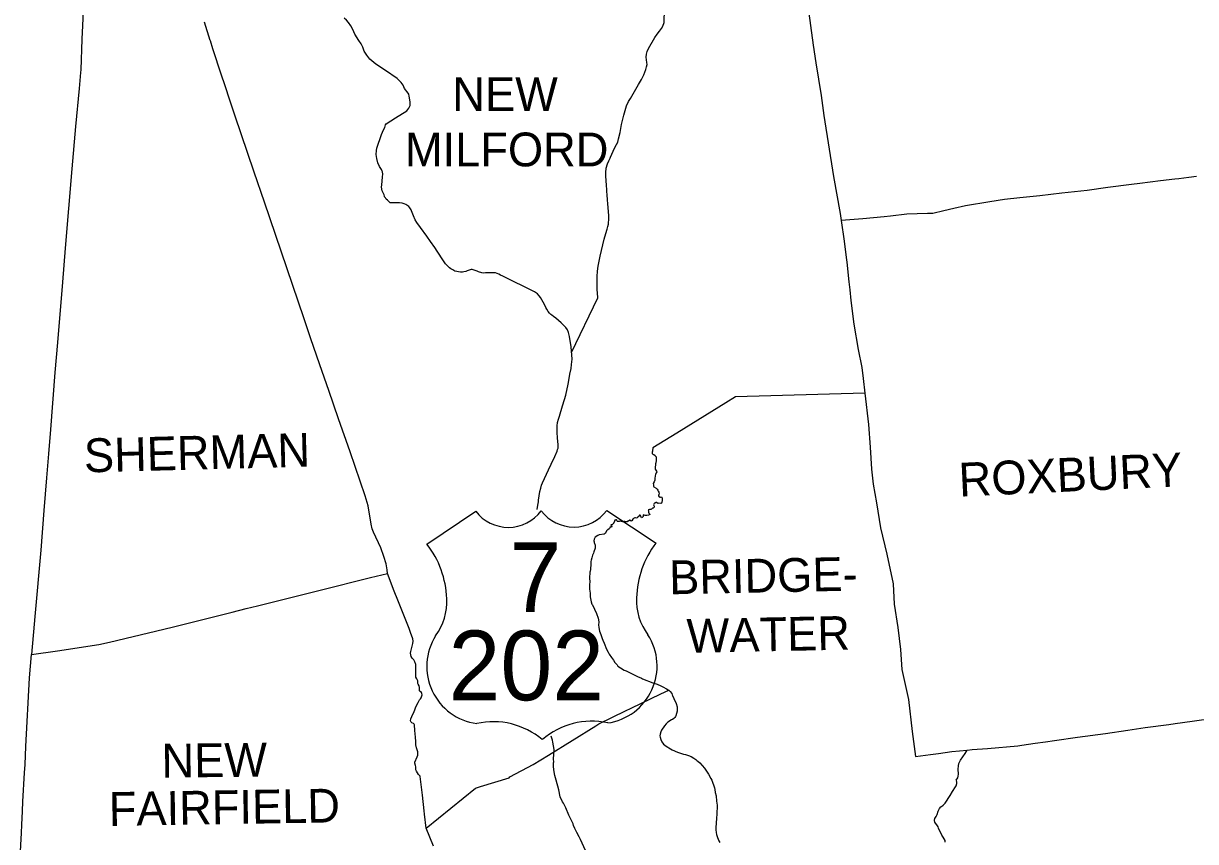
# Model space of a CAD drawing. Extents: x 0 to 2603, y -226 to 830.
# Drawn here: x 53.86 to 100.65, y 575 to 607.68 of the extents above; entities that cross this region are included whole.
import ezdxf

# ---------------------------------------------------------------- set-up
doc = ezdxf.new("R2010")
doc.units = 0
for name, color, linetype in [('CT_TSH_Map_Town_Limits', 7, 'Continuous'), ('CT_TSH_Map_Town_Text', 7, 'Continuous'), ('CT_TSH_Map_US_and_State_Routes', 7, 'Continuous')]:
    doc.layers.add(name, color=color, linetype=linetype)

msp = doc.modelspace()

# ---------------------------------------------------------------- linework, layer by layer
at = {"layer": 'CT_TSH_Map_Town_Limits'}
for points in [[(80.796, 620.456), (80.848, 619.874), (80.911, 619.122), (80.967, 618.543), (81.013, 617.971), (81.031, 617.779), (81.465, 614.798), (81.68, 614.608), (82.055, 614.284), (82.614, 613.822), (84.555, 612.035), (84.765, 611.835), (85.042, 609.477), (85.111, 608.892), (85.384, 606.809), (85.491, 606.099), (85.7, 604.798), (85.811, 603.998), (86.203, 601.565), (86.464, 600.083), (86.508, 599.804)], [(56.827, 616.808), (56.825, 616.707), (56.751, 615.439), (56.478, 611.587), (56.42, 610.703), (56.299, 609.259), (56.195, 607.042), (56.149, 605.817), (56.136, 605.715), (56.079, 605.082), (55.938, 603.558), (55.794, 601.866), (55.531, 598.701), (55.425, 597.346), (55.216, 594.938), (55.115, 593.729), (54.937, 591.45), (54.867, 590.481), (54.787, 589.52), (54.68, 588.216), (54.554, 586.636), (54.317, 583.992), (54.288, 583.676), (54.18, 582.466)], [(68.387, 585.703), (68.377, 585.847), (68.345, 586.091), (68.244, 586.389), (68.124, 586.725), (67.837, 587.355), (67.777, 587.493), (67.744, 587.67), (67.62, 588.403), (67.588, 588.539), (67.546, 588.678), (67.497, 588.81), (66.898, 590.569), (66.442, 591.878), (66.053, 593.009), (65.687, 594.044), (65.317, 595.115), (65.05, 595.92), (63.477, 600.54), (63.071, 601.737), (62.303, 604.016), (62.11, 604.573), (61.897, 605.225), (61.77, 605.608), (61.426, 606.66), (61.324, 606.977), (61.316, 606.997), (61.09, 607.721)], [(100.683, 601.568), (100.384, 601.525), (99.988, 601.474), (99.827, 601.46), (99.256, 601.391), (98.426, 601.289), (98.094, 601.244), (97.15, 601.119), (96.317, 601.004), (95.313, 600.892), (94.438, 600.789), (93.638, 600.713), (93.025, 600.64), (92.433, 600.546), (91.463, 600.385), (91.005, 600.283), (90.604, 600.193), (90.161, 600.088), (89.944, 600.078), (89.124, 600.055), (88.467, 599.974), (88.223, 599.955), (87.366, 599.871), (86.508, 599.804)], [(86.508, 599.804), (86.628, 598.975), (86.707, 598.33), (86.729, 598.136), (86.809, 597.357), (86.849, 597.032), (86.894, 596.607), (87.008, 595.663), (87.183, 594.65), (87.327, 593.937), (87.382, 593.49), (87.447, 592.904)], [(87.447, 592.904), (82.28, 592.76), (81.899, 592.525), (79.941, 591.312), (78.988, 590.723), (78.982, 590.713), (78.985, 590.699), (78.983, 590.669), (78.972, 590.646), (78.974, 590.595), (78.964, 590.547), (78.958, 590.538), (78.963, 590.502), (78.986, 590.476), (79.029, 590.458), (79.084, 590.411), (79.086, 590.389), (79.113, 590.359), (79.119, 590.346), (79.121, 590.274), (79.122, 590.217), (79.106, 590.13), (79.095, 590.09), (79.074, 589.918), (79.084, 589.875), (79.107, 589.838), (79.137, 589.795), (79.139, 589.769), (79.115, 589.731), (79.097, 589.664), (79.083, 589.601), (79.062, 589.504), (79.064, 589.438), (79.043, 589.372), (79.001, 589.305), (79.009, 589.241), (79.015, 589.187), (79.031, 589.169), (79.113, 589.114), (79.16, 589.067), (79.182, 589.036), (79.201, 588.991), (79.225, 588.955), (79.226, 588.947), (79.235, 588.912), (79.228, 588.857), (79.216, 588.816), (79.216, 588.801), (79.234, 588.768), (79.27, 588.752), (79.296, 588.756), (79.324, 588.761), (79.342, 588.754), (79.354, 588.691), (79.356, 588.621), (79.347, 588.555), (79.329, 588.51), (79.305, 588.506), (79.228, 588.517), (79.22, 588.513), (79.186, 588.504), (79.179, 588.504), (79.125, 588.536), (79.105, 588.537), (79.092, 588.532), (79.084, 588.522), (79.072, 588.515), (79.045, 588.518), (79.036, 588.503), (79.028, 588.475), (79.016, 588.452), (79.033, 588.392), (79.035, 588.354), (79.023, 588.334), (78.995, 588.32), (78.974, 588.315), (78.936, 588.276), (78.9, 588.259), (78.851, 588.257), (78.814, 588.242), (78.805, 588.227), (78.807, 588.215), (78.808, 588.176), (78.814, 588.161), (78.814, 588.154), (78.821, 588.116), (78.858, 588.086), (78.861, 588.068), (78.86, 588.06), (78.806, 588.036), (78.739, 588.022), (78.716, 588.021), (78.673, 588.025), (78.611, 588.047), (78.601, 588.039), (78.597, 587.984), (78.577, 587.959), (78.559, 587.943), (78.538, 587.934), (78.517, 587.952), (78.501, 587.996)], [(87.447, 592.904), (87.596, 591.65), (87.657, 590.744), (87.717, 589.876), (87.777, 589.266), (87.91, 588.528), (88.074, 587.527), (88.326, 586.475), (88.574, 585.294), (88.623, 584.473), (88.77, 583.546), (88.866, 582.674), (88.919, 581.875), (89.19, 580.673), (89.335, 579.391), (89.464, 578.389), (90.074, 578.479), (90.386, 578.52), (90.924, 578.589), (91.535, 578.652)], [(78.501, 587.996), (78.498, 588.011), (78.489, 588.024), (78.476, 588.032), (78.455, 588.028), (78.423, 588), (78.392, 587.958), (78.376, 587.949), (78.354, 587.924), (78.332, 587.916), (78.29, 587.928), (78.261, 587.921), (78.238, 587.909), (78.188, 587.888), (78.184, 587.88), (78.197, 587.863), (78.191, 587.849), (78.164, 587.844), (78.16, 587.809), (78.141, 587.804), (78.133, 587.802), (78.12, 587.801), (78.075, 587.838), (78.063, 587.84), (78.015, 587.795), (77.996, 587.789), (77.977, 587.788), (77.968, 587.784), (77.954, 587.769), (77.938, 587.762), (77.911, 587.766), (77.873, 587.786), (77.826, 587.781), (77.821, 587.779), (77.795, 587.767), (77.768, 587.762), (77.671, 587.789), (77.638, 587.783), (77.613, 587.776), (77.578, 587.787), (77.565, 587.799), (77.554, 587.821), (77.549, 587.849), (77.545, 587.853), (77.532, 587.846), (77.529, 587.838), (77.519, 587.829), (77.502, 587.831), (77.479, 587.847), (77.465, 587.83), (77.456, 587.796), (77.44, 587.753), (77.399, 587.705), (77.39, 587.67), (77.381, 587.662), (77.323, 587.646), (77.315, 587.635), (77.32, 587.622), (77.346, 587.602), (77.353, 587.587), (77.331, 587.561), (77.32, 587.561), (77.299, 587.574), (77.287, 587.576), (77.276, 587.564), (77.268, 587.528), (77.261, 587.507), (77.238, 587.491), (77.187, 587.446), (77.167, 587.439), (77.145, 587.425), (77.136, 587.403), (77.091, 587.316), (77.08, 587.3), (77.045, 587.279), (77.037, 587.276), (76.838, 587.242), (76.789, 587.219), (76.689, 587.151), (76.656, 587.105), (76.641, 587.073), (76.635, 587.009), (76.645, 586.969), (76.647, 586.942), (76.678, 586.839), (76.686, 586.763), (76.677, 586.714), (76.629, 586.567), (76.617, 586.52), (76.583, 586.438), (76.545, 586.327), (76.517, 586.24), (76.51, 586.178), (76.507, 586.014), (76.498, 585.939), (76.498, 585.874), (76.478, 585.778), (76.474, 585.769), (76.461, 585.502), (76.467, 585.379), (76.462, 585.247)], [(54.18, 582.466), (55.217, 582.619), (56.865, 582.874), (57.296, 582.959), (59.798, 583.563), (60.704, 583.793), (62.198, 584.162), (62.758, 584.302), (63.203, 584.418), (65.71, 585.043), (67.719, 585.542), (68.387, 585.703)], [(69.941, 575.53), (69.875, 576.089), (69.854, 576.218), (69.784, 576.846), (69.696, 577.589), (69.695, 577.606), (69.634, 577.674), (69.547, 577.814), (69.53, 577.859), (69.519, 577.903), (69.52, 577.977), (69.514, 578.031), (69.482, 578.134), (69.488, 578.165), (69.578, 578.376), (69.598, 578.45), (69.605, 578.5), (69.6, 578.574), (69.552, 578.739), (69.529, 578.866), (69.531, 578.903), (69.529, 578.989), (69.51, 579.171), (69.504, 579.293), (69.491, 579.437), (69.465, 579.655), (69.452, 579.685), (69.429, 579.706), (69.37, 579.736), (69.334, 579.766), (69.32, 579.786), (69.314, 579.822), (69.328, 579.896), (69.368, 579.995), (69.46, 580.19), (69.485, 580.259), (69.517, 580.332), (69.553, 580.437), (69.623, 580.549), (69.676, 580.653), (69.714, 580.704), (69.731, 580.735), (69.772, 580.857), (69.767, 580.911), (69.753, 580.955), (69.699, 580.995), (69.674, 581.022), (69.666, 581.047), (69.676, 581.11), (69.674, 581.15), (69.654, 581.216), (69.621, 581.279), (69.607, 581.314), (69.599, 581.411), (69.589, 581.447), (69.562, 581.498), (69.528, 581.567), (69.525, 581.586), (69.521, 581.696), (69.529, 582.02), (69.52, 582.074), (69.491, 582.171), (69.443, 582.249), (69.383, 582.32), (69.341, 582.39), (69.323, 582.449), (69.318, 582.524), (69.322, 582.588), (69.347, 582.689), (69.4, 582.905), (69.417, 583.001), (69.406, 583.096), (69.315, 583.353), (69.253, 583.502), (68.812, 584.636), (68.666, 585.002), (68.387, 585.703)], [(76.462, 585.247), (76.463, 585.083), (76.482, 584.922), (76.489, 584.771), (76.522, 584.575), (76.556, 584.477), (76.571, 584.451), (76.74, 584.103), (76.803, 583.916), (76.834, 583.776), (76.836, 583.758), (76.821, 583.652), (76.827, 583.546), (76.853, 583.404), (76.903, 583.261), (76.969, 583.104), (76.99, 583.035), (77.043, 582.919), (77.141, 582.677), (77.196, 582.562), (77.237, 582.487), (77.332, 582.343), (77.409, 582.243), (77.47, 582.15), (77.558, 582.049), (77.594, 582.009), (77.695, 581.935), (77.842, 581.845), (77.926, 581.81), (78.032, 581.757), (78.14, 581.71), (78.341, 581.604), (78.404, 581.579), (78.441, 581.559), (78.532, 581.525), (78.577, 581.499), (78.983, 581.34), (79.152, 581.277), (79.301, 581.219), (79.381, 581.173), (79.533, 581.101), (79.599, 581.059), (79.618, 581.045)], [(52.565, 558.217), (53.186, 565.312), (53.241, 566.29), (53.267, 566.696), (53.297, 567.249), (53.324, 567.68), (53.335, 567.948), (53.358, 568.186), (53.416, 569.104), (53.501, 570.509), (53.522, 570.8), (53.647, 572.974), (53.671, 573.348), (53.712, 574.105), (53.785, 575.347), (53.796, 575.66), (53.828, 576.207), (53.843, 576.6), (53.904, 577.741), (53.928, 578.079), (53.96, 578.799), (54.106, 581.531), (54.18, 582.466)], [(69.941, 575.53), (71.906, 577.132), (71.986, 577.156), (72.108, 577.198), (73.246, 577.546), (73.279, 577.578), (74.208, 578.07), (74.815, 578.443), (76.707, 579.617), (76.83, 579.694), (77.891, 580.215), (78.115, 580.323), (79.299, 580.896), (79.618, 581.045)], [(79.618, 581.045), (79.679, 580.997), (79.739, 580.915), (79.757, 580.858), (79.772, 580.825), (79.829, 580.707), (79.923, 580.506), (79.954, 580.383), (79.962, 580.263), (79.951, 580.2), (79.898, 580.02), (79.884, 579.989), (79.859, 579.952), (79.828, 579.918), (79.766, 579.872), (79.736, 579.858), (79.59, 579.768), (79.511, 579.704), (79.447, 579.625), (79.327, 579.445), (79.3, 579.376), (79.276, 579.285), (79.27, 579.22), (79.275, 579.169), (79.301, 579.068), (79.341, 578.979), (79.415, 578.886), (79.514, 578.813), (79.695, 578.698), (79.762, 578.656), (79.964, 578.568), (80.049, 578.542), (80.207, 578.488), (80.283, 578.468), (80.403, 578.434), (80.51, 578.393), (80.628, 578.329), (80.701, 578.278), (80.746, 578.239), (80.78, 578.213), (80.857, 578.143), (80.95, 578.04), (81.041, 577.929), (81.209, 577.688), (81.303, 577.517), (81.343, 577.442), (81.441, 577.14), (81.458, 577.079), (81.473, 576.962), (81.509, 576.822), (81.53, 576.612), (81.556, 576.448), (81.554, 576.299), (81.543, 576.226), (81.54, 576.105), (81.521, 575.916), (81.5, 575.559), (81.504, 575.459), (81.514, 575.364), (81.531, 575.272), (81.564, 575.154), (81.62, 575.031), (81.655, 574.96)], [(91.535, 578.652), (91.732, 578.669), (92.35, 578.717), (93.55, 578.818), (93.719, 578.846), (94.25, 578.923), (94.666, 578.983), (95.022, 579.027), (95.937, 579.163), (97.054, 579.319), (97.953, 579.448), (98.64, 579.552), (99.584, 579.677), (99.838, 579.709), (100.516, 579.801), (101.46, 579.938), (102.31, 580.059), (102.957, 580.139)], [(90.651, 574.967), (90.649, 575.034), (90.619, 575.103), (90.569, 575.171), (90.526, 575.248), (90.386, 575.536), (90.371, 575.582), (90.345, 575.629), (90.238, 575.771), (90.223, 575.837), (90.225, 575.857), (90.247, 575.918), (90.29, 575.991), (90.341, 576.081), (90.38, 576.209), (90.432, 576.314), (90.488, 576.377), (90.505, 576.403), (90.58, 576.455), (90.649, 576.529), (90.856, 576.832), (90.948, 577.001), (91.063, 577.183), (91.092, 577.224), (91.119, 577.322), (91.124, 577.363), (91.104, 577.439), (91.095, 577.45), (91.166, 577.539), (91.179, 577.611), (91.186, 577.683), (91.169, 577.891), (91.182, 578.019), (91.2, 578.115), (91.263, 578.251), (91.45, 578.517), (91.535, 578.652)], [(70.228, 574.817), (69.941, 575.53)]]:
    msp.add_lwpolyline(points, dxfattribs=at)
at = {"layer": 'CT_TSH_Map_US_and_State_Routes'}
for p, q in [((78.753, 606.041), (78.747, 606.114)), ((77.677, 603.323), (77.74, 603.635)), ((77.29, 602.341), (77.459, 602.697)), ((77.148, 601.038), (77.136, 601.204)), ((77.153, 600.969), (77.148, 601.038)), ((77.164, 600.835), (77.153, 600.969)), ((77.18, 600.63), (77.164, 600.835)), ((77.191, 600.475), (77.18, 600.63)), ((77.227, 600.007), (77.191, 600.475)), ((76.765, 597.346), (76.764, 597.361)), ((76.768, 597.037), (76.765, 597.346)), ((76.774, 596.915), (76.768, 597.037)), ((75.745, 594.53), (76.784, 596.714)), ((76.784, 596.714), (76.774, 596.915)), ((69.962, 586.878), (71.915, 588.194)), ((77.148, 588.225), (79.112, 586.919)), ((69.963, 586.88), (69.962, 586.878))]:
    msp.add_line(p, q, dxfattribs=at)
for points in [[(79.334, 607.469), (79.39, 607.565), (79.432, 607.709), (79.444, 607.793), (79.444, 607.884), (79.454, 608.061), (79.46, 608.121), (79.487, 608.244), (79.538, 608.542), (79.555, 608.702)], [(67.085, 607.247), (67.007, 607.44), (66.931, 607.58), (66.831, 607.72), (66.755, 607.803), (66.661, 607.885)], [(78.736, 606.443), (78.762, 606.55), (78.81, 606.677), (79.065, 607.111), (79.162, 607.244), (79.248, 607.363), (79.334, 607.469)], [(68.24, 603.42), (68.283, 603.52), (68.297, 603.575), (68.309, 603.632), (68.346, 603.671), (68.708, 603.909), (69.171, 604.191), (69.241, 604.29), (69.298, 604.392), (69.298, 604.54), (69.256, 604.767), (69.241, 604.848), (69.213, 604.894), (69.068, 605.071), (69.015, 605.205), (68.945, 605.314), (68.781, 605.479), (68.312, 605.791), (67.922, 606.051), (67.689, 606.253), (67.562, 606.415), (67.466, 606.572), (67.408, 606.733), (67.339, 606.864), (67.243, 606.99), (67.085, 607.247)], [(78.747, 606.114), (78.727, 606.229), (78.722, 606.325), (78.736, 606.443)], [(78.088, 604.676), (78.407, 605.243), (78.536, 605.44), (78.627, 605.63), (78.704, 605.831), (78.737, 605.948), (78.753, 606.041)], [(77.932, 604.383), (78.01, 604.554), (78.088, 604.676)], [(77.74, 603.635), (77.831, 604.015), (77.932, 604.383)], [(68.177, 601.771), (68.152, 601.848), (68.071, 601.964), (68.011, 602.113), (67.962, 602.276), (67.941, 602.442), (67.949, 602.595), (67.968, 602.7), (68.156, 603.242), (68.24, 603.42)], [(77.459, 602.697), (77.531, 602.837), (77.583, 602.939), (77.62, 603.062), (77.677, 603.323)], [(77.124, 601.899), (77.173, 602.068), (77.223, 602.192)], [(77.223, 602.192), (77.263, 602.269), (77.277, 602.297), (77.29, 602.341)], [(68.163, 601.22), (68.194, 601.55), (68.202, 601.649), (68.189, 601.751), (68.177, 601.771)], [(77.136, 601.204), (77.103, 601.583), (77.103, 601.721), (77.124, 601.899)], [(68.256, 600.836), (68.216, 600.905), (68.181, 600.984), (68.165, 601.051), (68.156, 601.153), (68.163, 601.22)], [(68.499, 600.517), (68.456, 600.553), (68.387, 600.618), (68.344, 600.662), (68.314, 600.704), (68.28, 600.754), (68.271, 600.783), (68.256, 600.836)], [(69.357, 600.193), (69.337, 600.232), (69.317, 600.27), (69.288, 600.31), (69.244, 600.359), (69.205, 600.393), (69.127, 600.447), (69.064, 600.477), (68.975, 600.502), (68.87, 600.514), (68.715, 600.512), (68.499, 600.517)], [(69.567, 599.725), (69.5, 599.827), (69.435, 599.997), (69.357, 600.193)], [(77.163, 599.462), (77.19, 599.561), (77.213, 599.655), (77.229, 599.898), (77.227, 600.007)], [(69.716, 599.521), (69.567, 599.725)], [(70.277, 598.723), (70.112, 598.964), (69.962, 599.176), (69.716, 599.521)], [(77.046, 599.053), (77.103, 599.287), (77.163, 599.462)], [(76.808, 597.983), (76.884, 598.377), (77.046, 599.053)], [(70.377, 598.579), (70.277, 598.723)], [(70.801, 597.977), (70.709, 598.077), (70.634, 598.2), (70.377, 598.579)], [(70.995, 597.833), (70.928, 597.871), (70.872, 597.91), (70.801, 597.977)], [(76.764, 597.361), (76.768, 597.57), (76.782, 597.786), (76.808, 597.983)], [(71.311, 597.744), (71.232, 597.748), (71.155, 597.762), (71.081, 597.786), (70.995, 597.833)], [(72.032, 597.756), (71.976, 597.778), (71.899, 597.803), (71.858, 597.819), (71.815, 597.838), (71.777, 597.845), (71.731, 597.843), (71.693, 597.839), (71.578, 597.788), (71.514, 597.767), (71.44, 597.75), (71.384, 597.744), (71.311, 597.744)], [(72.992, 597.579), (72.901, 597.623), (72.836, 597.664), (72.767, 597.694), (72.699, 597.709), (72.612, 597.715), (72.394, 597.712), (72.303, 597.714), (72.215, 597.705), (72.153, 597.711), (72.032, 597.756)], [(74.265, 596.958), (72.992, 597.579)], [(75.226, 595.804), (75.107, 595.897), (75.021, 595.966), (74.95, 596.023), (74.918, 596.045), (74.863, 596.101), (74.805, 596.168), (74.75, 596.258), (74.712, 596.329), (74.669, 596.424), (74.611, 596.543), (74.506, 596.729), (74.452, 596.798), (74.377, 596.875), (74.265, 596.958)], [(75.328, 595.714), (75.226, 595.804)], [(75.719, 594.756), (75.663, 595.169), (75.625, 595.327), (75.576, 595.444), (75.511, 595.535), (75.328, 595.714)], [(75.76, 594.27), (75.755, 594.433), (75.721, 594.741), (75.719, 594.756)], [(75.69, 593.72), (75.721, 593.899), (75.745, 594.059), (75.76, 594.27)], [(75.385, 592.404), (75.456, 592.648), (75.511, 592.83), (75.605, 593.262), (75.689, 593.731)], [(75.254, 591.99), (75.385, 592.404)], [(75.165, 591.598), (75.184, 591.74), (75.213, 591.872), (75.254, 591.99)], [(75.182, 591.128), (75.161, 591.341), (75.161, 591.536), (75.165, 591.598)], [(75.204, 590.768), (75.207, 590.844), (75.182, 591.128)], [(74.929, 590.068), (75.069, 590.384), (75.162, 590.596), (75.186, 590.663), (75.2, 590.71), (75.204, 590.768)], [(74.825, 589.849), (74.929, 590.068)], [(74.427, 588.639), (74.479, 588.978), (74.508, 589.11), (74.542, 589.237), (74.577, 589.329), (74.825, 589.849)], [(74.366, 588.259), (74.392, 588.428), (74.416, 588.565), (74.427, 588.639)], [(74.932, 579.201), (74.93, 579.206)], [(74.993, 578.968), (74.975, 579.046), (74.958, 579.122), (74.932, 579.201)], [(75.287, 576.778), (75.238, 577.067), (75.12, 577.451), (75.069, 577.634), (75.032, 577.859), (75.018, 578.005), (75.025, 578.136), (75.037, 578.178), (75.025, 578.29), (75.046, 578.678), (75.026, 578.818), (74.993, 578.968)], [(75.385, 576.582), (75.287, 576.778)], [(75.415, 576.526), (75.385, 576.582)], [(76.421, 574.334), (76.395, 574.428), (76.302, 574.643), (76.1, 575.081), (76.047, 575.188), (75.955, 575.357), (75.87, 575.523), (75.823, 575.643), (75.803, 575.71), (75.72, 575.86), (75.634, 576.047), (75.51, 576.34), (75.415, 576.526)]]:
    msp.add_lwpolyline(points, dxfattribs=at)
for centre, radius, start, end in [((73.216, 589.18), 1.632, 217.1377, 323.3979), ((75.834, 589.192), 1.632, 217.1377, 323.3979), ((67.036, 584.581), 3.722, 1.8086, 38.1428), ((82.057, 584.651), 3.722, 142.3929, 178.7271), ((68.528, 584.558), 2.232, 323.1742, 3.6193), ((80.565, 584.614), 2.232, 176.9164, 217.3614), ((72.271, 581.994), 2.308, 147.9382, 262.1377), ((76.847, 582.016), 2.308, 278.3979, 32.5975), ((72.621, 576.774), 3.009, 49.6665, 102.7966), ((76.545, 576.792), 3.009, 77.739, 130.8691)]:
    msp.add_arc(centre, radius, start, end, dxfattribs=at)

# ---------------------------------------------------------------- texts
at = {"layer": 'CT_TSH_Map_Town_Text'}
for s, p in [('NEW', (70.981, 604.18)), ('MILFORD', (69.089, 601.967))]:
    msp.add_text(s, height=1.35, dxfattribs=at).set_placement(p)
for s, rotation, p in [('SHERMAN', 1.4832, (56.292, 589.74)), ('ROXBURY', 2.7147, (91.227, 588.77)), ('BRIDGE-', 1.1574, (79.649, 584.871)), ('WATER', 1.1574, (80.349, 582.532)), ('NEW', 0.6103, (59.378, 577.549)), ('FAIRFIELD', 0.9118, (57.277, 575.619))]:
    msp.add_text(s, height=1.35, rotation=rotation, dxfattribs=at).set_placement(p)
at = {"layer": 'CT_TSH_Map_US_and_State_Routes'}
for s, height, p in [('7', 2.785, (73.26, 584.16)), ('202', 2.7853, (70.828, 580.639))]:
    msp.add_text(s, height=height, dxfattribs=at).set_placement(p)

doc.saveas('drawing.dxf')
